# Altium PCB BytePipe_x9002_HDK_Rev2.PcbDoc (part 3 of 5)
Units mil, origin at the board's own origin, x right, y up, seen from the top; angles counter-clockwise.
Board outline 4250 x 4250 mil, 8 copper layers (Top Layer, L2-GND, L3-SIG, L4-GND, L5-PWR, L6-SIG, L7-GND, Bottom Layer), stack 63 mil thick; 296 components, 250 nets, 1198 pads, 2326 vias.
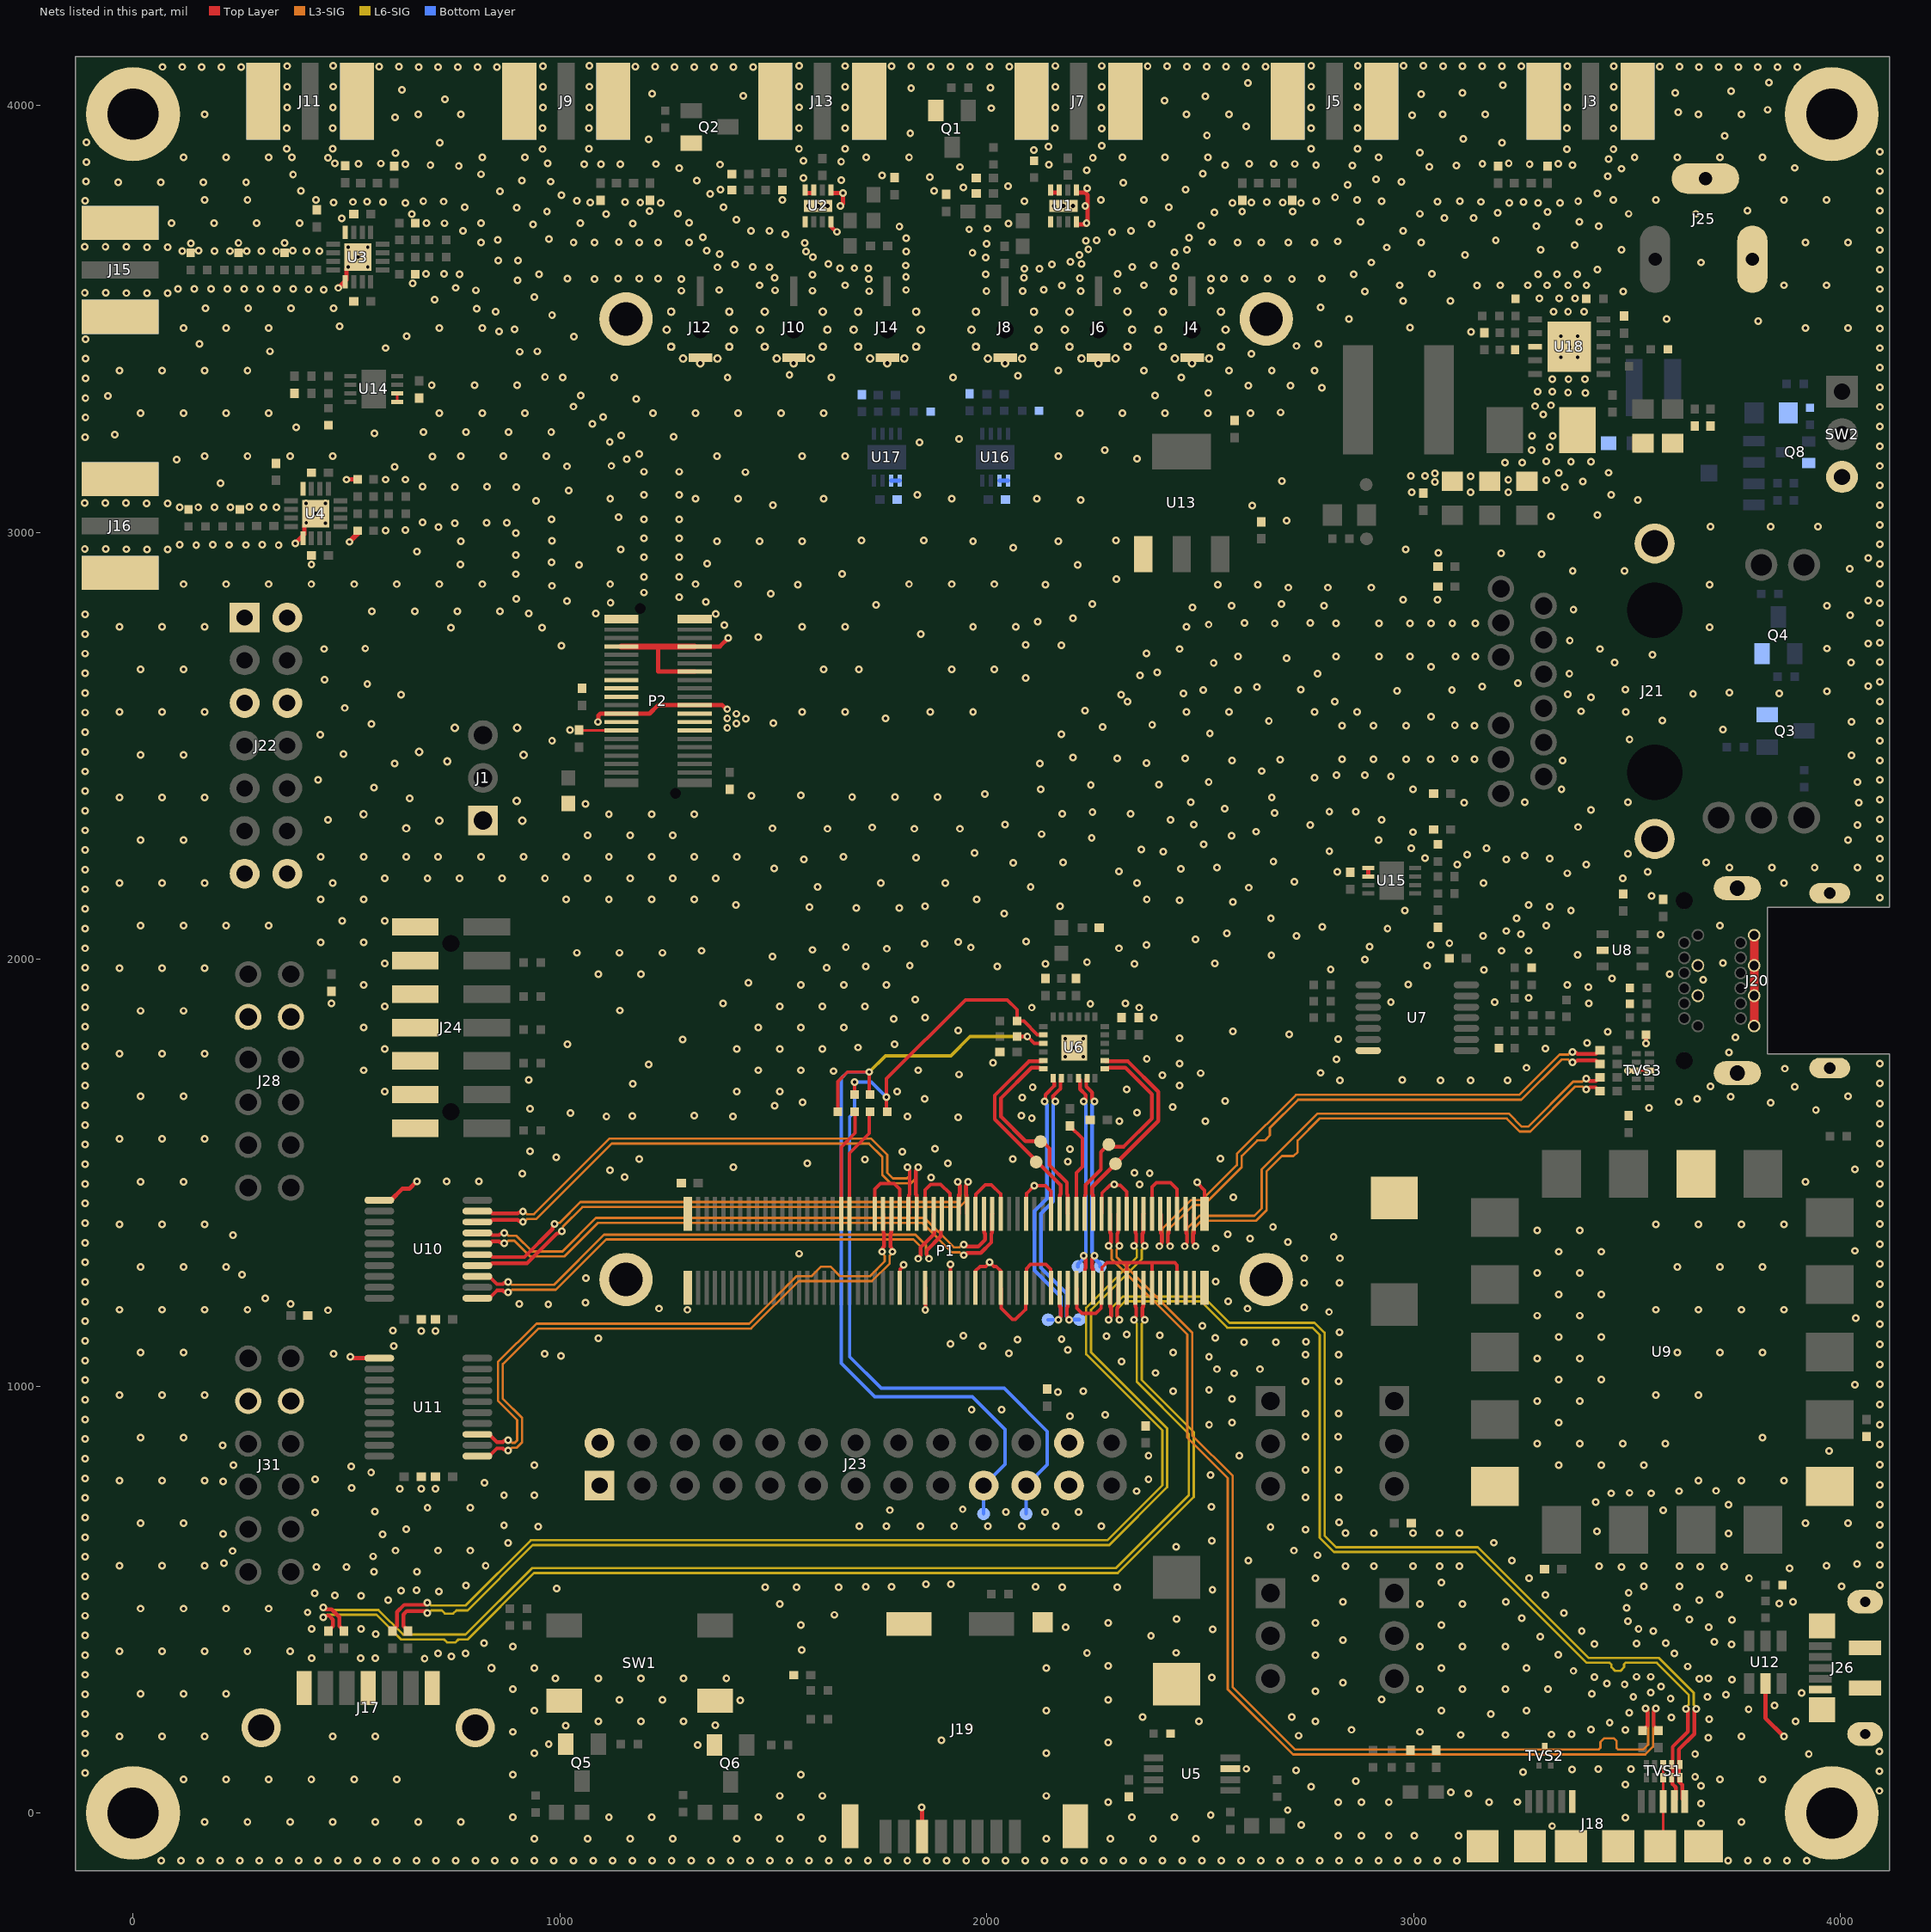
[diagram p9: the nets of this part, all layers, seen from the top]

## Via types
v1: diameter 18, hole 8, Top Layer to Bottom Layer, tented both sides, 2283 vias
v2: diameter 20, hole 10, Top Layer to Bottom Layer, tented both sides, 39 vias
v3: diameter 16, hole 8, Top Layer to Bottom Layer, tented both sides, 4 vias

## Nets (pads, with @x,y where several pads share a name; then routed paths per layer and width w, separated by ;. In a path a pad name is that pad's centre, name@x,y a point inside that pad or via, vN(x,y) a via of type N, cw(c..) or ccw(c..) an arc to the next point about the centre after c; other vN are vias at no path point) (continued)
GND: C1.2 C2.2 C3.2 C4.2 C5.2 C6.2 C7.2 C8.2 C9.2 C10.2 C11.2 C14.2 C15.2 C16.2 C17.2 C18.2 C19.2 C20.2 C23.2 C24.2 C26.2 C27.2 C28.2 C30.2 C33.2 C36.2 C37.2 C38.2 C39.2 C40.2 C43.2 C44.2 C45.2 C46.2 C47.2 C48.2 C49.2 C50.2 C51.2 C56.2 C57.2 C60.2 C61.1 C62.1 C63.1 C64.1 C65.2 C66.1 C67.2 C68.2 C69.1 C70.2 C71.2 C72.2 C73.1 C74.1 C75.2 C76.2 C77.2 C78.2 C79.2 C80.2 C82.2 C83.2 C85.2 C86.2 C88.2 C89.2 C91.2 C92.2 C93.2 C94.2 C95.2 C97.1 C98.2 C99.2 C100.2 C101.1 C102.1 C103.2 C104.2 D1.2 J1.1 J3.2 J4.2 J5.2 J6.2 J7.2 J8.2 J9.2 J10.2 J11.2 J12.2 J13.2 J14.2 J15.2 J16.2 J17.0 J17.1 J17.4 J17.7 J18.5 J18.8 J18.11 J18.12 J18.13 J18.14 J18.15 J18.16 J19.6 J19.M-1 J19.M-2 J19.M-3 J19.M-4 J20.0 J20.1 J20.7 J20.8 J20.13 J20.14 J20.19 J21.0 J22.1 J22.2 J22.5 J22.6 J22.13 J22.14 J23.1 J23.2 J23.23 J23.24 J24.1 J24.3 J24.5 J24.7 J24.9 J24.11 J24.13 J25.2 J25.3 J26.5 J26.SH J26.TH J28.5 J28.11 J31.5 J31.11 MH1.1 MH2.1 MH3.1 MH4.1 MH5.1 MH6.1 MH7.1 MH8.1 P1.05 P1.06 P1.11 P1.12 P1.17 P1.18 P1.23 P1.24 P1.29 P1.30 P1.35 P1.36 P1.41 P1.42 P1.47 P1.48 P1.53 P1.54 P1.59 P1.60 P1.65 P1.66 P1.71 P1.72 P1.77 P1.M1 P1.M2 P1.M3 P1.M4 P2.01 P2.02 P2.07 P2.08 P2.14 P2.15 P2.17 P2.19 P2.22 P2.23 P2.24 P2.25 P2.26 P2.27 P2.28 Q1.2 Q2.2 Q3.2 Q4.2 Q5.2 Q6.2 Q8.2 R2.1 R5.1 R13.2 R14.2 R15.2 R16.2 R17.2 R23.2 R24.2 R25.2 R26.2 R31.2 R38.1 R45.2 R46.2 R47.1 R50.1 R64.2 R67.1 R72.1 R74.1 R76.1 R80.1 R85.2 R86.2 R88.2 SW1.3 SW1.4 SW2.3 TVS1.3 TVS1.8 TVS2.3 TVS3.3 TVS3.8 U1.1 U1.3 U1.4 U1.5 U1.8 U1.9 U2.1 U2.3 U2.4 U2.5 U2.8 U2.9 U3.5 U3.16 U3.17 U4.5 U4.16 U4.17 U5.3 U6.25 U7.7 U8.2 U9.1 U9.7 U9.14 U10.11 U11.11 U12.5 U13.1 U14.5 U14.6 U15.5 U15.6 U16.5 U16.6 U17.5 U17.6 U18.8 U18.11 | length 4866.7
  Top Layer w6: R24.2@525.13,3123.91 R24.2@526.04,3124.81 ; U14.5@619,3306 U14.6@619,3326 ; C3.2@1045,2537 1045.9,2536.1 P2.27@1143.39,2536.1 ; C2.2@1393.39,2393.39 C2.2@1398,2398 ; TVS3.8@3524.5,1739 TVS3.3@3553.08,1739 TVS3.3@3555.5,1739 ; J18.15@3578,-78 3585,-71 TVS1.8@3585,82.5 TVS1.3@3585,113.5
  Top Layer w8: P1.77@1737.68,1403.61 1737.68,1461.68 1751,1475 1783.27,1475 1796.73,1461.54 P1.71@1796.73,1403.61 ; P1.72@1796.73,1230.39 1797.73,1231.39 1797.73,1274.03 1805,1281.29 v1(1805,1284) ; P1.65@1855.79,1403.61 1855.79,1459.79 1869,1473 1891.9,1473 1913.84,1451.06 1913.84,1404.61 P1.59@1914.84,1403.61 ; v1(1856.24,1178.31) 1857,1179.07 P1.66@1857,1231 ; P1.60@1914.84,1230.39 1915.42,1230.96 v1(1915.42,1285.42) ; P1.54@1973.9,1230.39 1973.9,1269.84 1984.44,1280.39 1997.39,1280.39 v1(2007,1290) 2016.61,1280.39 2022.41,1280.39 2032.95,1269.84 P1.48@2032.95,1230.39 2033.95,1229.39 2033.95,1182.94 2060.63,1156.26 2067.26,1156.26 2091.01,1180.01 2091.01,1229.39 P1.42@2092.01,1230.39 2093.01,1231.39 2093.01,1275.01 2102.93,1284.93 2120.93,1284.93 2138.93,1284.93 2150.06,1273.79 2150.06,1231.39 P1.36@2151.06,1230.39 ; P1.53@1973.9,1403.61 1974.9,1404.61 1974.9,1449.9 1997,1472 2011,1472 2033,1450 2033,1403.66 P1.47@2032.95,1403.61 ; P1.41@2092.01,1403.61 2093.01,1404.61 2093.01,1451 v1(2112.01,1470) 2138,1470 2151.06,1456.94 P1.35@2151.06,1403.61 ; C46.2@2195,1610 2195,1609 2224,1580 2224,1514 2210.12,1500.12 P1.29@2210.12,1403.61 ; P1.30@2210.12,1230.39 2211.12,1229.39 2211.12,1182.94 2223.67,1170.39 2255.56,1170.39 2268.17,1183 2268.17,1229.39 P1.24@2269.17,1230.39 2270.17,1231.39 2270.17,1277.77 2281.4,1289 2332,1289 ; P1.23@2269.17,1403.61 2270.17,1404.61 2270.17,1452.17 2289,1471 2312.84,1471 2328.23,1455.61 P1.17@2328.23,1403.61 ; P1.18@2328.23,1230.39 2328.23,1285.23 2332,1289 ; P1.12@2387.28,1230.39 2387.28,1289 ; P1.11@2387.28,1403.61 2387.28,1466.28 2398,1477 2431,1477 2446.34,1461.66 P1.05@2446.34,1403.61 ; P1.06@2446.34,1230.39 2446.34,1283.66 2441,1289 2387.28,1289 ; v1(2493,1478) 2493,1476.24 2510.31,1458.92 P1.M1@2510.31,1403.61 ; 2332,1289 2387.28,1289
  Top Layer w10: v1(380.14,2974.49) 401,2995.35 401,3017 U4.17@428,3044 ; v1(481,3572.96) 500,3591.96 500,3618 v1(504,3622) v1(527,3645) ; v1(500.04,3123.81) 500.13,3123.91 525.13,3123.91 525.91,3123.91 R24.2@526,3124 ; v1(509,1069) 511.16,1069 514.66,1065.5 U11.11@577,1065.5 ; U10.11@577,1435.5 604,1435.5 630.82,1462.32 647.32,1462.32 v1(665,1480) ; v1(1089.02,2555.86) 1090.55,2557.39 1090.55,2571.15 1094.87,2575.47 P2.23@1144,2575.47 1210.31,2575.47 1230,2595.16 P2.22@1316,2595.16 1380.68,2595.16 1389.84,2586 v1(1392,2586) ; P2.07@1143.39,2732.95 P2.07@1144,2732.95 ; 1230,2732.95 1230,2673.9 P2.14@1316,2673.9 P2.14@1316.61,2673.9 ; P2.08@1316,2732.95 1374.98,2732.95 v1(1394.79,2752.76) ; P2.02@1316,2797 P2.02@1317.35,2798.35 ; U2.4@1575,3795 U2.3@1595,3795 ; U2.8@1635,3721 1635,3717 1648.02,3703.98 v1(1648.88,3703.98) ; U2.1@1635,3795 v1(1663,3795) v1@1663,3770 ; v1(1848,13) 1848.5,12.5 1848.5,-60.5 J19.6@1849,-61 ; U1.4@2150,3796 U1.3@2170,3796 ; U1.8@2210,3722 2231,3722 v1(2233.93,3724.93) 2236.86,3727.86 2236.86,3790.14 2231,3796 U1.1@2210,3796 ; U15.6@2894,2194 U15.5@2894,2214 ; v1(3502,1739) TVS3.8@3522.08,1739 TVS3.8@3524.5,1739 ; v1(3545,1803) R50.1@3545,1823 ; U12.5@3824.5,303 3824.5,222.56 v1(3868.03,179.03)
  Top Layer w12: v1(507.04,2977.81) 526,2996.77 R23.2@526,3004
  Top Layer w14: P2.07@1144,2732.95 1230,2732.95 P2.08@1316,2732.95
  Top Layer w20: J20.1@3798.11,1843.7 J20.7@3798.11,1914.57 J20.13@3798.11,1985.43 J20.19@3798.11,2056.3
  Bottom Layer w10: U17.6@1776,3121 U17.5@1796,3121 ; U16.6@2030,3121 U16.5@2050,3121
  other v1: 66,-112 112,-112 158,-112 204,-112 250,-112 296,-112 342,-112 388,-112 434,-112 480,-112 526,-112 572,-112 618,-112 664,-112 710,-112 756,-112 802,-112 848,-112 894,-112 940,-112 986,-112 1032,-112 1078,-112 1124,-112 1170,-112 1216,-112 1262,-112 1308,-112 1354,-112 1400,-112 1446,-112 1492,-112 1538,-112 1584,-112 1630,-112 1676,-112 1722,-112 1768,-112 1814,-112 1860,-112 1906,-112 1952,-112 1998,-112 2044,-112 2090,-112 2136,-112 2182,-112 2228,-112 2274,-112 2320,-112 2366,-112 2412,-112 2458,-112 2504,-112 2550,-112 2596,-112 2642,-112 2688,-112 2734,-112 2780,-112 2826,-112 2872,-112 2918,-112 2964,-112 3010,-112 3056,-112 3102,-112 3737,-112 3783,-112 3829,-112 3875,-112 3921,-112 940,-60 1065,-60 1165,-60 1265,-60 1415,-60 1515,-60 1615,-60 2140,-60 2290,-60 2390,-60 2490,-60 3105.37,-53.63 2823.19,-53.06 2878,-53 2942,-53 3001.77,-53.06 3324.72,-30.53 2736.76,-28.45 3674,-24 168.03,-20.97 268.03,-20.97 368.03,-20.97 468.03,-20.97 568.03,-20.97 668.03,-20.97 768.03,-20.97 3768.03,-20.97 3496,-11 890,-10 1115,-10 1215,-10 1465,-10 1565,-10 2340,-10 2440,-10 2525,-5 2705.27,6.7 3674,22 2285,25 2823.19,24.94 2878,25 2942,25 3177.54,25.7 3243.82,25.86 1515,40 1615,40 2140,40 3128.44,45.4 3087.1,48.63 4092,52 2760.42,61.85 3674,64 3496,67 2865,75 118.03,79.03 218.03,79.03 318.03,79.03 418.03,79.03 518.03,79.03 618.03,79.03 3718.03,79.03 3818.03,79.03 3660,85 890,90 1565,90 -112,94 3257.13,95.55 4092,98 2725,100 3371.23,102.09 2608.57,103.4 3433.16,102.78 3509.17,103.01 3660,138 3926,138 -112,140 940,140 2140,140 4092,144 1323,159 974,161 2285,165 1894,170 3691.15,176.15 -31.97,179.03 68.03,179.03 168.03,179.03 468.03,179.03 568.03,179.03 3768.03,179.03 2731,181 3111,183 3215,183 3323,184 3370.84,184.51 -112,186 890,190 3015,190 3496.81,194.37 2855,195 3415.4,195.65 1960,202 1014,205 1364,206 3459.61,211.31 2497.67,214.29 1090,215 1190,215 1290,215 2770,215 3895,215 3693,220 3604,224 2365,225 2715,225 -112,232 3181,232 3505.85,234.85 940,240 2140,240 3065,240 3265,240 3785,243 3846,252 1423,264 1140,265 1240,265 2285,265 2925,266 3602.59,268.26 3515,272 3689.15,271.85 3732,277 -112,278 18.03,279.03 118.03,279.03 218.03,279.03 3418.03,279.03 3909,281 3556,282 2770,285 890,290 3015,290 3115,290 3215,290 3315,290 3580,296 3494.85,301.15 3453,303 2835,305 3746,312 3670,314 990,315 1090,315 1190,315 1290,315 1390,315 3691,315 2527.32,317.03 3424,318 3523,319 3556,319 -112,324 3375,333 940,340 2140,340 3065,340 3265,340 3642.15,343.15 2285,345 683,362 419,363 533,363 568,363 746,367 -112,370 2770,370 3339,371 715,374 779,374 3611.15,374.15 2235,375 2443.55,375.31 -31.97,379.03 68.03,379.03 168.03,379.03 268.03,379.03 368.03,379.03 1567,382 890,390 3015,390 3115,390 3215,390 3745,395 3424,396 3523,397 822,398 3591,398 3704.85,401.15 2835,405 3297,413 2385,415 -112,416 569,419 3394.15,426.15 3562,426 2529.31,430.41 419,431 534,431 3527.15,430.85 2185,435 3692,435 1565,440 3065,440 2285,445 2770,445 3502,449 3746,452 3646.15,453.15 2444.88,454.27 3254,456 -112,462 1643,464 3352.15,468.15 409,470 18.03,479.03 118.03,479.03 218.03,479.03 318.03,479.03 3499,481 3617.15,481.15 1515,490 3015,490 3115,490 3857,491 2835,495 3216,495 3889,495 598,499 3670,499 -112,508 534,509 473,510 3309.15,511.15 3717,512 426,515 3504,516 717,519 628,521 664,522 2529.02,522.99 993,526 1481,529 1555,529 1653,529 2177,529 2306,529 1717,530 1777,530 2115,530 3540,531 3623,531 4003,531 780,533 4093,534 1858,536 1916,536 3065,540 2770,550 3271.15,550.15 3786,550 -112,554 565,565 665,565 3881,573 430,576 500,576 3487.77,576.23 3672,577 3728,577 2841,578 2907,578 2999,578 3061,578 3108,578 3435,578 3540,578 3623,578 -31.97,579.03 68.03,579.03 168.03,579.03 826,579 3968.03,579.03 4093,581 4039,583 213,585 2613.39,591.09 3230.15,591.15 -112,600 563,601 2775,604 233,614 615,615 715,615 790,615 2720,615 2444.31,623.39 4093,628 879,633 3188.15,633.15 2527.14,637.67 -112,646 585,653 211,654 3738,655 2841,656 2907,656 2999,656 3061,656 3108,656 3430,660 2747,664 640,665 2665,670 949,671 1702,672 1765,672 1844.4,672 1923.8,672 2003.2,672 2082.6,672 2162,672 2269,672 869.29,673.58 4093,675 18.03,679.03 118.03,679.03 3918.03,679.03 4018.03,679.03 2826,681 -112,692 427,704 2045,705 2137.14,705 2215,705 567,706 3585,709 1773.28,709.65 1943.91,711.69 690,715 790,715 2526.21,717.08 3738,722 4093,722 3427,728 -112,738 2747,739 2825,739 869.29,744.29 940,744.29 3463,749 3557,749 3506,750 2351,754 3622,754 3709,755 625,760 675,760 709,760 511.85,761.15 4093,769 823.58,773.58 211,777 -31.97,779.03 68.03,779.03 168.03,779.03 3668.03,779.03 3768.03,779.03 3868.03,779.03 427,782 2379,782 -112,784 2524.66,791.84 558,798 2747,804 2825,804 511,812 235,815 940,815 3340,815 3440,815 3540,815 4093,816 -112,830 2379,837 2591.94,836.89 3974,848 210,861 4093,863 3290,865 3390,865 3490,865 3590,865 -112,876 18.03,879.03 118.03,879.03 3818.03,879.03 2747,881 2824,881 2521.01,909.48 4093,910 2575,915 3340,915 -112,922 2195,930 2277.81,932.79 2747,936 2825,936 1965,945 2035,945 4093,957 3290,965 3390,965 -112,968 2575,970 -31.97,979.03 68.03,979.03 168.03,979.03 3568.03,979.03 3668.03,979.03 2167,986 2226.25,988.46 2437,988 2521,991 4034,1003 4093,1004 2747,1011 2825,1011 -112,1014 3340,1015 3440,1015 2580,1030 2396,1031 2540,1040 2640,1040 4093,1051 2316,1058 -112,1060 3290,1065 3390,1065 2521,1069 1003,1071 2747,1074 2825,1074 470,1076 964,1076 2052,1077 18.03,1079.03 118.03,1079.03 2437,1079 3618.03,1079.03 3718.03,1079.03 3818.03,1079.03 2189.81,1084.9 611,1094 1991,1094 4093,1098 1915,1099 2603,1103 2678,1103 2748,1104 -112,1106 2072,1109 2175.54,1110.43 1090,1112 2536,1113 3340,1115 3440,1115 2281,1117 1945,1118 2405.95,1119.39 2328,1121 2827,1126 675,1129 709,1129 609,1130 2505,1141 4093,1145 -112,1152 4036,1159 3290,1165 3390,1165 2802,1173.95 457,1178 -31.97,1179.03 68.03,1179.03 168.03,1179.03 268.03,1179.03 1299,1179 3568.03,1179.03 3668.03,1179.03 3768.03,1179.03 3868.03,1179.03 1232,1182 2611,1182 2744,1184.62 973,1192 4093,1192 369,1193 905,1193 1060,1196 -112,1198 2566,1199 310.15,1205.85 3340,1215 3440,1215 4093,1239 2744,1242.23 2827,1241.9 -112,1244 2537,1245 1061.15,1253.15 255,1261 3290,1265 3390,1265 18.03,1279.03 118.03,1279.03 218.03,1279.03 3618.03,1279.03 3718.03,1279.03 3818.03,1279.03 4093,1286 -112,1290 2744,1299.85 2828,1299.85 1561,1310 3340,1315 3440,1315 4034,1317 2537,1323 4093,1333 -112,1336 2706,1338 2616.85,1345.85 2813,1350 233.85,1353.85 2565.15,1356.15 3290,1365 3390,1365 2671,1373 -31.97,1379.03 68.03,1379.03 168.03,1379.03 3568.03,1379.03 3668.03,1379.03 3768.03,1379.03 3868.03,1379.03 4093,1380 -112,1382 4093,1427 -112,1428 2578.29,1442.07 2299,1473 2358,1473 -112,1474 4093,1474 18.03,1479.03 118.03,1479.03 3918.03,1479.03 735,1480 810,1480 1870,1489 1151.85,1490.15 912,1498 2382,1499 2346.33,1500 1117.49,1505.88 4034,1508 1407,1513 -112,1520 4093,1521 1580,1522 1909,1522 2190,1526 1714.69,1530.63 1186,1532 2061,1532 2548,1533 992,1536 1802,1549 930,1550 2195,1555 1879,1556 -112,1566 4093,1568 -31.97,1579.03 68.03,1579.03 168.03,1579.03 -112,1612 4093,1615 2311,1621 2512,1621 2106,1627.78 1933,1630 1109,1632 1406,1632 1814.86,1632 1170,1633 1315,1634 2081,1634 1025,1640 2352,1641 3943,1647 930,1650 3552,1652 2436,1654 1503.29,1657.05 -112,1658 4093,1662 3837,1664 1569,1665 3621,1666 2559,1668 1855,1673 3665,1673 2083,1676 3743,1678 18.03,1679.03 118.03,1679.03 4018.03,1679.03 590,1690 1415,1690 1515,1690 1790,1690 2328,1695 2108,1700 3893,1701 3696,1702 -112,1704 2452,1704 1171,1708 4093,1709 2828,1716 3063,1716 3134,1716 3220,1716 927,1717 2974,1717 2412,1728 1935,1730 2501,1733 2782,1734 1641,1738 540,1740 1465,1740 1565,1740 1840,1740 3870,1744 3265,1746 -112,1750 1208,1754 2452,1756 4093,1756 2014.54,1757.29 2820,1766 2375,1767 2184,1772 2226,1772 -31.97,1779.03 68.03,1779.03 168.03,1779.03 3739,1782 590,1790 1415,1790 1515,1790 1615,1790 3309,1791 1698.58,1793.42 2205,1793 -112,1796 1018,1801 1784,1801 3407,1804 1288,1812 2824,1812.67 2184,1814 2226,1814 2452,1815 3754,1817 2709,1824 3455,1830 2577,1831 1933,1833 540,1840 1465,1840 1565,1840 1665,1840 -112,1842 1782.58,1860.42 1856,1863 2391.25,1863 18.03,1879.03 118.03,1879.03 1141,1880 2106,1887 2357,1887 -112,1888 590,1890 1515,1890 1615,1890 1715,1890 2243,1896 465,1897 1382,1897 2325,1897 3411,1897 2947,1900 3190,1900 1832.58,1905.42 3270,1910 -112,1934 3410,1935 540,1940 1565,1940 1665,1940 1765,1940 3360,1940 2988,1941 1442,1945 3679,1952 3465,1955 1090,1965 1190,1965 3600,1965 3165,1975 2806,1976 -31.97,1979.03 68.03,1979.03 168.03,1979.03 -112,1980 1625,1980 1717,1983 2025,1983 1820,1985 3032,1985 2138,1989 2346.33,1989 590,1990 2535,1990 3725,1991 2235,1993 2886,1999 1498,2006 2667,2009 3385,2010 1040,2015 1140,2015 1240,2015 1332,2020 3206,2020 3270,2020 1592,2022 1766,2025 -112,2026 2310,2026 1963,2028 1670,2029 2897,2030 3040,2033.47 2374,2034 1855,2037 3084,2038 440,2040 540,2040 1933,2041 2092,2042 2489,2047 2726,2055 3163,2055 3579,2058 3252,2059 2563,2061 3217,2066.33 -112,2072 2939,2072 2786,2076 18.03,2079.03 118.03,2079.03 218.03,2079.03 318.03,2079.03 3311.37,2079 3718.03,2079.03 490,2090 590,2090 2666,2096 3241.37,2096 2041,2107 2980,2114 3368.99,2114 -112,2118 1695,2120 1795,2120 1585,2122 3319,2122.89 1856,2124 2172,2124 1413,2127 3270,2127.07 2577,2134 2452,2138 440,2140 540,2140 1015,2140 1115,2140 1215,2140 1315,2140 1977,2140 2375,2140 4093,2144 3558,2148 -112,2164 2614,2168 1604,2170 2103,2170 -31.97,2179.03 68.03,2179.03 168.03,2179.03 468.03,2179.03 1752,2179 1903,2179 2352,2179 3164,2179 3868.03,2179.03 2721,2182 590,2190 690,2190 765,2190 865,2190 965,2190 1065,2190 1165,2190 1265,2190 1365,2190 3490,2190 4093,2190 3360,2201.33 2822,2205 3548.61,2205.07 2310,2206 -112,2210 2455,2212 1502,2213 2540,2215 3740,2215 3840,2215 3940,2215 4040,2215 3103,2222 3405,2222 2062,2226 2179,2227 3686,2227 2672,2229 1572,2234 3217,2234 3319,2236 4093,2236 3027,2237 1835,2238 440,2240 540,2240 640,2240 715,2240 815,2240 915,2240 1015,2240 1115,2240 1215,2240 1315,2240 1415,2240 1664,2240 3261,2242.77 3126,2245 3502,2247.32 1972,2249 2414,2252 2803,2253 -112,2256 2362,2257 2995,2260 3171,2260 2508,2269 18.03,2279.03 118.03,2279.03 2918.03,2279.03 4018.03,2279.03 4093,2282 2246,2284 2574,2289 1065,2290 1165,2290 1265,2290 2129,2293 2999,2298 2631,2299 -112,2302 1627,2306 1831,2306 1937,2306 1498,2307 1732,2309 3386,2310 2758,2315 4040,2315 2043,2316 2485,2316 457,2327 2431,2327 2924.98,2327 4093,2328 1115,2340 1215,2340 1315,2340 2177,2341 2337,2341 2675,2343 2248,2345 2803,2346.23 2864.98,2346.23 -112,2348 3416,2350 2558,2353 1060,2364 3119,2367 4043,2367 2478,2368 3261,2368.33 3502,2368.33 4093,2374 648,2377 -31.97,2379.03 68.03,2379.03 168.03,2379.03 2668.03,2379.03 1685,2380 1785,2380 1885,2380 1449,2383 1565,2384 1996,2387 -112,2394 2127,2398 2999,2398 3346.82,2398 565,2402 2244,2408 2404,2409 2520,2415 4040,2415 434,2420 4093,2420 2768,2425 2947,2428 2820,2431.63 2886,2431.63 -112,2440 2644,2441 613,2459 2125,2459 2374,2460 2575.01,2466 3349.55,2466 4093,2466 2687.28,2468 2833,2469 2906,2469 2983,2469 3040,2469 3143,2469 3097,2470 2306,2471 2465,2471 2202,2473 4026,2478 18.03,2479.03 118.03,2479.03 493,2481 -112,2486 982,2512 4093,2512 3506,2515 439,2526 2175,2527 2523,2529 -112,2532 1023.98,2537.08 3725,2538 1392,2542 2272,2544 2833,2547 2906,2547 2983,2547 3143,2547 3097,2548 2388,2549 559,2551 1414,2552 1500,2553 4026,2556 2661,2558 4093,2558 3583,2559 1436,2563 1392,2564 1762.73,2564 3041,2568 1414,2575 -112,2578 -31.97,2579.03 68.03,2579.03 168.03,2579.03 1568.03,2579.03 1668.03,2579.03 1868.03,2579.03 1968.03,2579.03 2468.03,2579.03 2568.03,2579.03 2768.03,2579.03 2868.03,2579.03 3497.23,2579.03 3393,2581 2230.15,2582.15 496,2589 2330,2604 2815.74,2604 4093,2604 3416,2613.72 628,2620 2315,2620 3361,2621 3655,2622 2461,2623 3857,2623 -112,2624 3740,2625 3969,2628 2962,2629 2507,2631 2589,2631 3090,2631 2736,2632 3496,2632 2633,2638 3161,2639 4065,2640 549,2645 3245,2647 4093,2650 449,2655 2091,2659 2359,2665 2775.37,2669 3365,2669 -112,2670 2400,2672 18.03,2679.03 118.03,2679.03 1618.03,2679.03 1701,2679 1918.03,2679.03 2018.03,2679.03 3041,2685 2532,2694 3471,2695 4025,2695 4093,2696 2703,2705 2589,2709 2819,2709 2919,2709 2992,2709 3099,2709 3145,2709 3560,2713 -112,2716 2374.33,2716.67 448,2727 2452.25,2727 3437,2727 544,2728 3969,2728 1003.53,2734.59 2175,2736 2091,2737 4065,2740 4093,2742 3366,2747 1465,2755 -112,2762 1846,2762 745,2777 958.32,2777.09 3694,2778 -31.97,2779.03 68.03,2779.03 168.03,2779.03 1568.03,2779.03 1668.03,2779.03 1968.03,2779.03 2068.03,2779.03 2468.03,2779.03 1385.66,2782.5 2520,2784.37 2675.03,2787 2819,2787 2919,2787 2992,2787 3041,2787 3091,2787 3145,2787 2604.12,2788 2758,2788.02 4093,2788 2119.85,2791.15 2202,2799.26 4023,2806 -112,2808 1365,2809 926.85,2809.86 1084.16,2809.86 560,2815 660,2815 760,2815 860,2815 3375,2819 2482.63,2824.37 2573.55,2828 2789.99,2828 3969,2828 1741,2830 2247.63,2832.41 2691.04,2832.41 4093,2834 1119,2835 1342,2837 1016.98,2839.03 4065,2840 2975.66,2842 3056,2842 897.62,2844.3 1280,2848 1494,2856 1197,2859 2707,2871 2799.37,2871 2901.08,2871 981.55,2875.02 1558,2878 2138,2878 2541.63,2878 2634.99,2878 3694,2878 118.03,2879.03 218.03,2879.03 318.03,2879.03 418.03,2879.03 518.03,2879.03 618.03,2879.03 718.03,2879.03 818.03,2879.03 1118.03,2879.03 1318.03,2879.03 1418.03,2879.03 1818.03,2879.03 1918.03,2879.03 2018.03,2879.03 4093,2880 2304.32,2890.72 1197,2896 1280,2896 897.19,2902.27 1661,2903 3373,2910 3494,2910 4022,2915 1045,2924 2212.9,2924 418.04,2924.81 767,2925 4093,2926 1345,2927 980.25,2930.39 4065,2940 1197,2942 1280,2942 897.19,2947.26 3300,2949 3205,2951 3058,2952 665,2955 32.76,2960.23 81.27,2960.23 1143,2960 2982.02,2960.37 -112.76,2960.86 -64.25,2960.86 -15.74,2960.67 2062,2964.26 148.14,2970.47 341.48,2970.47 109.47,2970.97 186.81,2970.97 225.47,2970.72 264.14,2970.72 302.81,2970.97 4093,2972 768.03,2979.03 1368.03,2979.03 1468.03,2979.03 1568.03,2979.03 1968.03,2979.03 2168.03,2979.03 981.98,2980.57 1707,2981 1853,2981 2303.37,2981 1197,2986 1280,2986 896.84,2998.86 592.04,3004.81 638.04,3005.81 716.04,3012.81 3696.23,3013.23 3836.38,3013.23 3947.45,3013.23 4093,3018 451.04,3021.81 754,3022 875.44,3022.2 406,3023 828.7,3022.55 678.04,3023.81 2703,3027.58 980.94,3030.62 1197,3031 1280,3031 1138,3036 3321.96,3037.62 3430.73,3041 428.04,3044.81 109.19,3058.95 153.14,3059.23 190.9,3058.66 228.37,3059.23 272.89,3059.51 305.78,3059.3 336.36,3059.01 2621.79,3062.5 1499,3064 4093,3064 32.25,3068.16 80.76,3068.16 405.04,3067.81 451.04,3067.81 -113.28,3068.78 -64.77,3068.78 -16.26,3068.59 944.23,3074.1 2220.12,3075.65 3525.77,3075.84 1118.03,3079.03 1318.03,3079.03 1418.03,3079.03 1618.03,3079.03 1918.03,3079.03 2118.03,3079.03 1197,3088 1280,3088 1838,3088 3463,3088 2996,3094 3134,3094 3222,3094 1021,3098 754,3106 898.29,3106.33 3354,3106 678.04,3106.81 829.39,3107.02 4093,3110 205,3115 3050,3118 3397,3119 2692.07,3120.12 3311,3122 3222,3123 592.04,3123.81 638.04,3123.81 3134,3131 2994,3132 3027,3132 3050,3138 3340,3139 3457.07,3139.96 1435,3141 1197,3142 1280,3142 612.61,3153.87 1017,3155 1121,3156 4093,3156 3214,3164 3255,3164 3369,3166 3416,3166 3311,3167 102,3171 1157,3172 2352,3172.6 702,3178 168.03,3179.03 268.03,3179.03 368.03,3179.03 468.03,3179.03 768.03,3179.03 868.03,3179.03 968.03,3179.03 1368.03,3179.03 1568.03,3179.03 1668.03,3179.03 2168.03,3179.03 1186,3184 2276.37,3193 3277,3193 3319,3200 4093,3202 1843,3211 1117,3212 1935,3219 -112,3223 1267,3224 3278,3226 3326,3226 1144,3227 -43,3229 566,3232 680,3235 780,3235 880,3235 980,3235 382,3246 4093,3248 1076,3254 -111.63,3269 1101,3270 3304,3276 18.03,3279.03 118.03,3279.03 218.03,3279.03 318.03,3279.03 718.03,3279.03 818.03,3279.03 918.03,3279.03 1218.03,3279.03 1318.03,3279.03 1418.03,3279.03 1518.03,3279.03 1618.03,3279.03 2218.03,3279.03 2318.03,3279.03 2418.03,3279.03 2518.03,3279.03 2618.03,3279.03 2689,3281 4093,3294 1032,3295 3285,3296 3322,3298 1179,3313 -111.63,3315 -59,3320 1049,3321 2395,3321 2519,3327 3403,3327 3362,3328 3291,3330 3325,3330 2785.42,3338.74 4093,3340 2613,3344 2712,3344 700,3345 800,3345 900,3345 3325,3359 3363,3359 3402,3359 -111.44,3361 1007,3363 1128,3363 1393,3363 1636,3363 1921,3363 2456,3363 965,3364 2073,3367 1538,3369 -31.97,3379.03 68.03,3379.03 168.03,3379.03 268.03,3379.03 2168.03,3379.03 2368.03,3379.03 2568.03,3379.03 2668.03,3379.03 2768.03,3379.03 4093,3386 -111,3407 3345,3410 3385,3410 2620,3418 906,3423 321,3424 947,3424 592,3432 4093,3432 3365,3435 2726,3437 156,3442 2777,3442 -111,3453 1033,3459 641,3460 3345,3460 3385,3460 3135,3470 858,3471 894,3476 4093,3478 118.03,3479.03 218.03,3479.03 318.03,3479.03 718.03,3479.03 818.03,3479.03 3918.03,3479.03 4018.03,3479.03 2992,3480 484,3483 3808,3495 2848.42,3500 3592.74,3500 982,3509 850,3517 3327.96,3517 3361.98,3517 3399.63,3517 805,3524 4093,3524 170,3525 270,3525 370,3525 470,3525 2782,3527 2975.99,3542.62 3086.74,3542.62 707,3545 3294.96,3548.5 3341.37,3548.5 3378.33,3548.5 940,3551 32.77,3560.45 81.28,3560.45 -112.76,3561.08 -64.25,3561.08 -15.74,3560.89 1725,3565 1999.34,3565.46 2084.74,3565.29 2437.66,3564.86 2886.38,3564.56 3491.65,3564.56 1285,3566 1592,3566 2220.12,3565.72 2306.36,3565.92 2525.01,3566.41 803,3567 1504,3567 1373,3568 1811,3568 446.83,3568.91 2133.81,3568.69 144.01,3570.42 337.35,3570.42 375.67,3570.19 411.4,3569.9 4093,3570 105.35,3570.92 182.68,3570.92 221.35,3570.67 260.02,3570.67 298.69,3570.92 756,3573 2175.64,3578.39 3148.74,3578.39 1468.03,3579.03 1668.03,3579.03 2368.03,3579.03 2968.03,3579.03 3203.65,3579.03 3267.98,3579.03 3313.02,3579.03 3362,3579.03 3405.26,3579.03 3868.03,3579.03 3968.03,3579.03 654.87,3583.31 901,3591 1723.91,3593.39 1081.35,3593.96 1136.42,3594.49 1186.16,3594.44 1284.96,3594.07 2658.59,3594.47 2715.3,3594.02 2785.42,3594.47 1017.81,3595.02 1230.22,3594.81 2217.96,3595.3 2525.41,3594.83 2555.87,3594.91 2604.1,3594.91 2436.97,3596.09 1502.83,3596.66 2087,3597 1810.93,3598.33 1591.56,3603.49 1997.98,3604.3 765,3605 951.09,3604.55 2307.09,3605.43 2859.55,3604.74 3042.98,3605.43 3292.02,3604.74 3335.96,3604.74 3383.33,3604.74 686.88,3606 728.62,3605.8 3430.73,3616 4093,3616 2088,3618 2124,3618 1656.63,3618.84 1690.07,3619.35 1723.21,3619.16 1369.38,3621.32 1490.85,3621.35 550,3622 1451.91,3621.67 2340.81,3621.56 2442.89,3623.94 1810.59,3625.39 2391.23,3625.73 1410.37,3628.17 2153,3628 1629.07,3628.8 2222,3629 2901.53,3632.43 3674,3632.43 2196,3634 856,3637 902.38,3637.38 1998,3644 1592.67,3645.3 2217,3650 3121.02,3650 1374.03,3651.85 1967,3655 2439.56,3656.33 1577,3658 1811.09,3657.86 115.1,3659.52 190.96,3659.28 226.87,3659.17 266.27,3658.89 300.54,3658.89 335.54,3659.25 406.15,3659.25 436.44,3659.5 153.77,3660.03 374.1,3660 1344.33,3660.47 2469.24,3662.35 3297.9,3662 3487.01,3662 4093,3662 2238,3663 32.6,3668.39 81.11,3668.39 504,3668 550,3668 2937.7,3667.7 -112.93,3669.02 -64.42,3669.02 -15.91,3668.82 3377.26,3673.5 2000,3676 135.13,3677.11 246.91,3678.2 354.9,3677.93 1574.14,3678.04 815,3679 1032.39,3678.93 1081.35,3679.33 1186.16,3679.44 1230.22,3679.33 1302.52,3678.96 2587.58,3679.32 2642.96,3678.87 2706.84,3679.46 2768,3678.95 3018.03,3679.03 3918.03,3679.03 4018.03,3679.03 1138.17,3679.88 2528.63,3679.76 2822.88,3681.76 2232,3683 2257.61,3684.06 3192.74,3684.06 855,3685 974.9,3686.97 1811.09,3689.76 2473.98,3690.06 1335.39,3691.68 1528.83,3698.53 2293.52,3703.24 773.4,3706.09 1448.05,3706.08 1491.14,3706.38 2975.66,3706.11 2338.51,3706.73 4093,3708 1959,3710 2002,3712 1795.79,3716.21 3287.74,3717.38 3434.35,3717.38 2502.5,3718.57 937.51,3721.95 2386.35,3722.88 687.29,3724.32 730.04,3724.12 815.44,3724.25 1171,3724 2051,3724 90,3725 190,3725 290,3725 390,3725 1048,3725 1302.48,3725.41 2875.82,3727.3 3389.01,3727.3 1413.39,3732.3 489,3736 3072.01,3737 3141.02,3737 653,3745.81 1108.42,3745.56 3015.41,3746.3 3504.01,3746.3 3661.5,3746.3 1277,3747 3197.16,3748.53 2533.44,3749.86 3314.17,3750.77 970,3752 2598.52,3751.75 2716.52,3751.75 1209.92,3752.57 3782.55,3754 4093,3754 898.92,3760.55 776.83,3762.18 1383.56,3761.83 2426.41,3762.08 2230.91,3764.49 1657,3765 637.97,3772.35 1236.24,3771.9 2575.86,3772.12 2736.5,3771.77 3224.41,3772.2 3291.67,3772.12 3343.64,3771.75 469.64,3772.69 1071.05,3772.98 1188.52,3773.13 2620.02,3772.81 2693.39,3772.81 515.03,3774.38 585.48,3773.7 1152.73,3773.55 2656.88,3773.86 3158.31,3774.44 3257.45,3773.54 548.9,3774.72 727.38,3775.39 3056.49,3774.88 679.97,3775.73 2088,3776 2772.31,3776.29 2925.34,3776.25 3108.74,3776.22 3386.07,3776.22 -112,3777 1039.71,3776.9 168.03,3779.03 268.03,3779.03 428.66,3778.78 1521,3779 2268.03,3779.03 2368.03,3779.03 2868.03,3779.03 3468.03,3779.03 3568.03,3779.03 3868.03,3779.03 3968.03,3779.03 2816.12,3784.98 1004.15,3790.46 1352.52,3792.87 3430.73,3794.08 393.44,3800.12 859.52,3799.55 1877,3800 4093,3800 1376,3803 2466.47,3803.01 2235.02,3806.12 1945,3808 2050,3811 2846.03,3814.19 2320,3819 -35,3820 65,3820 165,3820 265,3820 2972.01,3821.21 -110,3822 978.83,3821.8 911,3824 1321.18,3824.51 1659.61,3825.44 2912,3827 1570.58,3830.27 1867,3832 3455.29,3834.27 1755,3836 374.81,3838.39 815.29,3838.94 2506.54,3840.03 4093,3846 2234.81,3848.56 3487,3852 1279.89,3853.14 3893,3854 1937,3856 3037.46,3856.5 763.47,3858.42 697.01,3860.24 2558.36,3860.5 2856.51,3859.77 3100.64,3859.92 3372.91,3860.39 2145.8,3861.52 2771.74,3860.94 1375,3862 638.13,3862.82 1057.49,3862.78 1096.66,3862.78 1141.57,3862.78 1225.04,3863.09 2721.67,3863.11 3161.54,3863.33 3272.27,3862.61 3339.68,3863.38 528.14,3863.86 580.64,3864.12 2615.41,3863.55 2672.89,3863.55 473.2,3864.77 971.6,3864.89 3223,3865 -109.56,3868 1658.9,3868.79 1571.12,3870.58 3457.07,3874.47 372.56,3878.36 457.12,3877.63 2249,3878 118.03,3879.03 218.03,3879.03 318.03,3879.03 818.03,3879.03 918.03,3879.03 1718.03,3879.03 1818.03,3879.03 2318.03,3879.03 2418.03,3879.03 2518.03,3879.03 2918.03,3879.03 3518.03,3879.03 3618.03,3879.03 3718.03,3879.03 3818.03,3879.03 615,3889 3015,3890 4093,3892 2110.94,3895.91 959.7,3898.26 3359.7,3898.26 3468.64,3898.17 360.52,3898.61 468,3898.86 1068.43,3898.85 1560.2,3899.01 1668.18,3898.64 2759.99,3898.82 2868.83,3898.99 2145.13,3903.71 2269.66,3905.71 719,3913 3207,3913 -109.37,3914 1208,3921 3117,3922 3729,3929 2516,3930 1821,3935 2269.66,3946.22 360.52,3947.12 468,3947.37 959.7,3946.77 1068.43,3947.36 1560.2,3947.52 1668.18,3947.15 2160.13,3947.22 2759.99,3947.33 2868.83,3947.5 3359.7,3946.76 3468.64,3946.68 2608,3951 614,3972 2997,3977 168.03,3979.03 668.03,3979.03 768.03,3979.03 2468.03,3979.03 2568.03,3979.03 3068.03,3979.03 3168.03,3979.03 3668.03,3979.03 3768.03,3979.03 3620,3984 3830,3990 2011,3994 960.14,3995.28 3360.14,3995.27 3469.08,3995.19 360.95,3995.63 468.43,3995.87 1068.86,3995.87 1560.63,3996.03 1668.61,3995.66 2160.57,3995.73 2269.1,3995.73 2760.42,3995.84 2869.27,3996.01 2417,4012 731,4015 2512,4022 1430,4023 3018,4027 1216,4028 3115,4030 3613,4030 3744,4034 630,4037 1823,4041 2009,4042 361.15,4044.14 468.63,4044.38 960.33,4043.79 1069.06,4044.38 1668.8,4044.17 2160.76,4044.24 2269.29,4044.24 2760.62,4044.35 2869.46,4044.52 3360.33,4043.78 3469.27,4043.7 1560.83,4044.54 3209,4048 2612,4053 3833,4054 161,4090.44 207,4090 253,4090 715,4090.37 761,4090.37 807,4090 853,4090 1315,4090.37 1361,4090.37 1407,4090 1453,4090 3715,4090.37 3761,4090.37 3807,4090 3853,4090 3899,4090 69,4090.63 115,4090.63 577,4091 623,4091 669,4090.56 1177,4091 1223,4091 1269,4090.56 1915,4091.37 1961,4091.37 2007,4091 2053,4091 2515,4091.37 2561,4091.37 2607,4091 2653,4091 3577,4091 3623,4091 3669,4090.56 960.33,4092.3 1777,4092 1823,4092 1869,4091.56 2377,4092 2423,4092 2469,4091.56 3115,4092.37 3161,4092.37 3207,4092 3253,4092 3360.33,4092.29 3469.27,4092.21 361.15,4092.65 468.63,4092.89 1069.06,4092.88 1560.83,4093.05 1668.8,4092.68 2160.76,4092.74 2269.29,4092.74 2760.62,4092.86 2869.46,4093.03 2977,4093 3023,4093 3069,4092.56
  other v2: 840,340 640,2307 718.03,2325 912,2325 540,2340 898.81,2371.17 736.31,2464 915,2479.03 670,2486 754,2542 900,2542
GTR_REFCLK0_N: P1.34 TP9.1 U6.13 | length 699.9
  Top Layer w8.75: v1(2135.92,1666.99) 2137.69,1668.76 2137.69,1682.69 2158.13,1703.13 2158.13,1711.63 2157.63,1712.13 2157.63,1719.38 U6.13@2156,1721 ; P1.34@2170.75,1230.39 2171.37,1229.76 2171.37,1185.88 2173.22,1184.04 2173.22,1163.1
  Bottom Layer w8.75: 2141.04,1659.36 2141.04,1439.05 2112.22,1410.23 2112.22,1271.07 2173.18,1210.1 2173.18,1163.07 2168.06,1157.95 v1(2168.06,1155.44) TP9.1@2143.82,1155.44
GTR_REFCLK0_P: P1.32 TP5.1 U6.14 | length 699.9
  Top Layer w8.75: v1(2160.92,1666.99) 2160.92,1669.49 2155.73,1674.69 2155.73,1679.87 2172.88,1697.02 2172.88,1711.63 2173.38,1712.12 2173.38,1719.38 U6.14@2175,1721 ; 2187.97,1163.04 2187.97,1184.04 2189.81,1185.88 2189.81,1229.76 P1.32@2190.43,1230.39
  Bottom Layer w8.75: 2155.79,1659.36 2155.79,1432.94 2126.97,1404.12 2126.97,1277.18 2187.93,1216.21 2187.93,1163.07 2193.06,1157.95 v1(2193.06,1155.44) 2193.34,1155.72 2216.72,1155.72 TP5.1@2217,1156
GTR_REFCLK1_N: P1.31 TP10.1 U6.12 | length 488.6
  Top Layer w8.75: U6.12@2133,1744 2131.38,1745.62 2124.12,1745.62 2123.62,1746.12 2104.98,1746.12 2033.75,1674.89 2033.75,1631.29 2091.04,1574 2130,1574 2147,1557 2147,1518.04 2187.97,1477.07 2187.97,1449.96 2189.81,1448.12 2189.81,1404.24 P1.31@2190.43,1403.61
GTR_REFCLK1_P: P1.33 TP8.1 U6.11 | length 490.3
  Top Layer w8.75: U6.11@2133,1763 2131.38,1761.38 2124.12,1761.38 2123.62,1760.88 2098.88,1760.88 2019,1681 2019,1625.18 2173.22,1470.96 2173.22,1449.96 2171.37,1448.12 2171.37,1404.24 P1.33@2170.75,1403.61
GTR_REFCLK2_N: P1.28 TP6.1 U6.16 | length 528.3
  Top Layer w8.75: U6.16@2215,1721 2218.62,1717.38 2218.62,1695.52 2232.27,1681.87 2232.27,1672.48 v1(2227.17,1667.38) ; P1.28@2229.8,1230.39 2230.43,1231.01 2230.43,1274.89 2232.27,1276.73 2232.27,1297.73
  Bottom Layer w8.75: TP6.1@2214,1280 2214,1285.75 2225.41,1297.16 2225.41,1303.56 v1(2227.18,1305.33) 2227.18,1307.83 2232.3,1312.96 2232.3,1498.63 2232.3,1659.75 2227.17,1664.88 v1(2227.17,1667.38)
GTR_REFCLK2_P: P1.26 TP2.1 U6.17 | length 527.7
  Top Layer w8.75: U6.17@2235,1721 2233.38,1719.38 2233.38,1701.62 2247.02,1687.98 2247.02,1672.53 v1(2252.17,1667.38) ; 2247.02,1297.67 2247.02,1276.73 2248.86,1274.89 2248.86,1231.01 P1.26@2249.49,1230.39
  Bottom Layer w8.75: v1(2252.17,1667.38) 2252.17,1664.88 2247.05,1659.75 2247.05,1504.74 2247.05,1312.96 2252.18,1307.83 v1(2252.18,1305.33) 2253.95,1303.56 2253.95,1297.8 2266,1285.75 TP2.1@2266,1280
GTR_REFCLK3_N: P1.25 TP1.1 U6.20 | length 506.8
  Top Layer w8.75: P1.25@2249.49,1403.61 2248.86,1404.24 2248.86,1448.12 2247.02,1449.96 2247.02,1466.02 2402,1621 2402,1689.86 2330.98,1760.88 2286.37,1760.88 2285.87,1761.37 2278.62,1761.37 U6.20@2277,1763
GTR_REFCLK3_P: P1.27 TP3.1 U6.19 | length 506.4
  Top Layer w8.75: P1.27@2229.8,1403.61 2230.43,1404.24 2230.43,1448.12 2232.27,1449.96 2232.27,1472.13 2267.57,1507.43 2267.57,1548.57 2280,1561 2321.14,1561 2387.25,1627.11 2387.25,1683.75 2324.88,1746.12 2286.37,1746.12 2285.87,1745.63 2278.62,1745.63 U6.19@2277,1744
GTR_RX0_N: J18.10 P1.22 TVS1.1 TVS1.10 | length 2423.4
  Top Layer w8.75: v1(2286.17,1155.44) 2286.17,1157.95 2291.33,1163.1 2291.33,1184.04 2289.48,1185.88 2289.48,1229.76 P1.22@2288.86,1230.39 ; J18.10@3635.78,27 3629.56,33.22 3629.56,66 3621.9,73.66 3621.9,149 3658,185.1 v1@3658,243
  L6-SIG w5.5: v1(2286.17,1155.44) 2286.17,1158.17 2292.92,1164.92 2292.92,1183.93 2318.97,1209.98 2507.29,1209.98 2568.76,1148.5 2768.15,1148.5 2791.63,1125.03 2791.63,649.64 2818.48,622.79 3150.83,622.79 3410.12,363.5 3574.5,363.5 3656.35,281.65 3656.35,253.62 3662.6,247.37 v1(3662.6,244.14)
GTR_RX0_P: J18.9 P1.20 TVS1.2 TVS1.9 | length 2423.4
  Top Layer w8.75: P1.20@2308.54,1230.39 2307.92,1229.76 2307.92,1185.88 2306.08,1184.04 2306.08,1163.04 2311.17,1157.95 v1(2311.17,1155.44) ; TVS1.9@3604.69,82.5 3606.31,80.88 3606.31,68.39 3607.15,67.55 ; J18.9@3610.78,27 3614.56,30.78 3614.56,60.14 3607.15,67.55 ; v1@3643.25,243 3643.25,191.21 3607.15,155.11 3607.15,67.55
  L6-SIG w5.5: v1(2311.17,1155.44) 2311.17,1158.17 2304.42,1164.92 2304.42,1179.16 2323.73,1198.48 2502.52,1198.48 2564,1137 2763.39,1137 2780.13,1120.26 2780.13,644.87 2813.71,611.29 3146.07,611.29 3405.35,352 3459,352 3463.74,347.26 3463.74,341.26 3472,333 3485,333 3493.46,341.46 3493.46,348.65 3496.81,352 ; 3497,352 3569.74,352 3644.85,276.89 3644.85,253.62 3638.6,247.37 v1(3638.6,244.14)
GTR_RX1_N: C34.1 P1.16 | length 2816.1
  Top Layer w8.75: v1(446,482) 450.63,477.38 v1@452.5,477.38 ; v1@452.5,477.25 465.23,477.25 483.38,459.11 483.38,437.62 494,427 C34.1@494,426 ; v1(2345.22,1155.44) 2345.22,1157.95 2350.38,1163.1 2350.38,1184.04 2348.54,1185.88 2348.54,1229.76 P1.16@2347.91,1230.39
  L6-SIG w5.5: v1(446,482) 449.22,482 455.47,475.75 575,475.75 632.75,418 779.24,418 934.74,573.5 2302.5,573.5 2473.9,744.9 2473.9,887.87 2351.97,1009.8 2351.97,1145.97 2345.22,1152.72 v1(2345.22,1155.44)
GTR_RX1_P: C35.1 P1.14 | length 2816.3
  Top Layer w8.75: v1(446,458) 450.5,462.5 459.12,462.5 468.62,453 468.62,437.62 458,427 C35.1@458,426 ; P1.14@2367.6,1230.39 2366.97,1229.76 2366.97,1185.88 2365.13,1184.04 2365.13,1163.04 2370.22,1157.95 v1(2370.22,1155.44)
  L6-SIG w5.5: v1(446,458) 449.22,458 455.47,464.25 570.24,464.25 627.99,406.5 728.5,406.5 735.4,399.6 755.6,399.6 762.5,406.5 784,406.5 939.5,562 2307.26,562 2485.4,740.14 2485.4,892.63 2363.47,1014.56 2363.47,1145.97 2370.22,1152.72 v1(2370.22,1155.44)
GTR_RX2_N: P1.10
GTR_RX2_P: P1.08
GTR_RX3_N: P1.04
GTR_RX3_P: P1.02
GTR_TX0_N: C42.1 P1.21 | length 2448.8
  Top Layer w8.75: v1(2286.17,1328.67) 2286.17,1331.18 2291.33,1336.33 2291.33,1357.27 2289.48,1359.11 2289.48,1402.99 P1.21@2288.86,1403.61 ; v1@3562.88,245 3562.88,212.89 3562.88,204.75 3568,199.62 3568.38,199.62 3574,194 C42.1@3574,193
  L3-SIG w5.5: v1(2286.17,1328.67) 2286.17,1325.95 2292.92,1319.2 2292.92,1297.95 2469.98,1120.9 2469.98,879.72 2565,784.7 2565,289.74 2717.74,137 3543,137 3561.25,155.25 3561.25,235.53 3567.5,241.78 v1(3567.5,245)
GTR_TX0_P: C41.1 P1.19 | length 2449.6
  Top Layer w8.75: P1.19@2308.54,1403.61 2307.92,1402.99 2307.92,1359.11 2306.08,1357.27 2306.08,1336.27 2311.17,1331.18 v1(2311.17,1328.67) ; C41.1@3537,193 3537,194 3542.62,199.62 3543,199.62 3548.12,204.75 3548.12,219 v1@3548.13,245
  L3-SIG w5.5: v1(2311.17,1328.67) 2311.17,1325.95 2304.42,1319.2 2304.42,1302.72 2481.48,1125.66 2481.48,884.48 2576.5,789.46 2576.5,294.5 2722.5,148.5 3433.5,148.5 3438,153 3438,166 3447,175 3469,175 3476,168 3476,152 3479.5,148.5 3538.24,148.5 3549.75,160.01 3549.75,235.53 3543.5,241.78 v1(3543.5,245)
GTR_TX1_N: C32.1 P1.15 | length 2731.2
  Top Layer w8.75: C32.1@608,426 608,427 618.62,437.62 618.62,471.11 635.27,487.75 v1@687,487.75 ; v1(2345.22,1328.67) 2345.22,1331.18 2350.38,1336.33 2350.38,1357.27 2348.54,1359.11 2348.54,1402.99 P1.15@2347.91,1403.61
  L6-SIG w5.5: v1(689.09,492.39) 692.32,492.39 698.57,486.14 779,486.14 931.86,639 2282.5,639 2411.5,768 2411.5,896.26 2233.14,1074.63 2233.14,1183.56 2351.97,1302.4 2351.97,1319.2 2345.22,1325.95 v1(2345.22,1328.67)
GTR_TX1_P: C31.1 P1.13 | length 2731.4
  Top Layer w8.75: C31.1@644,426 644,427 633.38,437.62 633.38,465 641.38,473 v1@687,473 ; P1.13@2367.6,1403.61 2366.97,1402.99 2366.97,1359.11 2365.13,1357.27 2365.13,1336.27 2370.22,1331.18 v1(2370.22,1328.67)
  L6-SIG w5.5: v1(689.09,468.39) 692.32,468.39 698.57,474.64 723,474.64 ; 723.5,474.5 730.8,467.2 750.2,467.2 757.64,474.64 783.76,474.64 936.62,627.5 2287.26,627.5 2423,763.24 2423,901.02 2244.64,1079.39 2244.64,1178.8 2363.47,1297.64 2363.47,1319.2 2370.22,1325.95 v1(2370.22,1328.67)
GTR_TX2_N: C55.1 P1.09 | length 1339
  Top Layer w8.75: v1(2404.9,1328.05) 2404.9,1330.55 2410.06,1335.71 2410.06,1356.65 2408.22,1358.49 P1.09@2408.22,1402.36 ; P1.09@2406.97,1403.61 P1.09@2407.59,1402.99 ; v1(3372.15,1782.84) 3373.92,1781.07 3381.21,1781.07 3384.07,1778.21 3412.87,1778.21 3427.21,1778.21 3436,1787 C55.1@3437,1787
  L3-SIG w5.5: v1(2404.9,1328.05) 2404.9,1330.77 2411.65,1337.52 2411.65,1368.56 2479.03,1435.94 2504.07,1435.94 2586.24,1518.11 2586.24,1543.91 2724.78,1682.45 3247.94,1682.45 3342.08,1776.59 3362.68,1776.59 3368.93,1782.84 v1(3372.15,1782.84)
GTR_TX2_P: C54.1 P1.07 | length 1330.3
  Top Layer w8.75: P1.07@2426.03,1402.99 P1.07@2426.65,1403.61 ; P1.07@2426.65,1402.36 2426.65,1358.49 2424.81,1356.65 2424.81,1335.64 2429.9,1330.55 v1(2429.9,1328.05) ; v1(3372.15,1758.84) 3373.92,1760.61 3381.21,1760.61 3384.07,1763.46 3406.76,1763.46 3427.21,1763.46 3436,1754.67 C54.1@3437,1754.67
  L3-SIG w5.5: v1(2429.9,1328.05) 2429.9,1330.77 2423.15,1337.52 2423.15,1363.8 2483.79,1424.44 2508.83,1424.44 2597.74,1513.34 2597.74,1539.15 2634.24,1575.65 2651.93,1575.65 2663.64,1587.35 2663.64,1605.05 2729.54,1670.95 3252.7,1670.95 3346.84,1765.09 3362.68,1765.09 3368.93,1758.84 v1(3372.15,1758.84)
GTR_TX3_N: C53.1 P1.03 | length 1319.1
  Top Layer w8.75: v1(2463.96,1328.05) 2463.96,1330.55 2469.12,1335.71 2469.12,1356.65 2467.27,1358.49 P1.03@2467.27,1402.36 ; P1.03@2466.02,1403.61 P1.03@2466.65,1402.99 ; v1(3405,1720) 3407.5,1720 3412.63,1714.88 3427.54,1714.88 3436,1723.33 C53.1@3437,1723.33
  L3-SIG w5.5: v1(2463.96,1328.05) 2463.96,1330.77 2470.71,1337.52 2470.71,1370.95 2498.7,1398.94 2626.84,1398.94 2644.28,1416.38 2644.28,1507.73 2775.05,1638.5 3223.09,1638.5 3253.59,1608 3268.74,1608 3373.99,1713.25 3395.53,1713.25 3402.28,1720 v1(3405,1720)
GTR_TX3_P: C52.1 P1.01 | length 1316.2
  Top Layer w8.75: P1.01@2485.08,1402.99 P1.01@2485.71,1403.61 ; P1.01@2485.71,1402.36 2485.71,1358.49 2483.87,1356.65 2483.87,1335.64 2488.96,1330.55 v1(2488.96,1328.05) ; v1(3405,1695) 3407.5,1695 3412.63,1700.12 3426.88,1700.12 3436,1691 C52.1@3437,1691
  L3-SIG w5.5: v1(2488.96,1328.05) 2488.96,1330.77 2482.21,1337.52 2482.21,1366.19 2503.46,1387.44 2631.6,1387.44 2655.78,1411.62 2655.78,1502.96 2691.82,1539 2719,1539 2728.57,1548.57 2728.57,1575.76 2779.82,1627 3218.32,1627 3248.82,1596.5 3273.5,1596.5 3378.75,1701.75 3395.53,1701.75 3402.28,1695 v1(3405,1695)
I2C1_SCL: J23.19 R33.2 R100.1 R102.1 TP7.1 U6.9 | length 2085.9
  Top Layer w8: R102.1@1651,1643 1651,1713 1674,1736 v1(1725,1736) R100.1@1725,1683 ; R33.2@2071,1819 2096,1819 2112,1803 U6.9@2133,1803
  L6-SIG w8: v1(1725,1736) 1763,1774 1916,1774 1961,1819 v1(2095,1819)
  Bottom Layer w8: v1(1725,1736) 1674,1736 1659,1721 1659,1054 1738,975 1967,975 2043,899 2043,817 J23.19@1993,767 TP7.1@1992.98,700.8
I2C1_SDA: J23.21 R34.2 R101.1 R103.2 TP4.1 U6.8 | length 2087.8
  Top Layer w8: R101.1@1691,1683 v1@1690.99,1712.01 ; R103.2@1765,1643 v1(1765,1677) 1765,1720 1950,1905 2048,1905 2071,1882 R34.2@2071,1855 2087,1855 2119,1823 U6.8@2133,1823
  L6-SIG w8: v1(1690.98,1712.02) v1@1692.02,1713.07
  Bottom Layer w8: v1(1765,1677) 1729.98,1712.02 v1(1690.98,1712.02) 1690.98,1642.98 1679,1631 1679,1069 1753,995 2041,995 2142,894 2142,816 J23.21@2093,767 2092.66,766.66 2092.66,701.09 TP4.1@2092.32,700.75
I2C1_SELECT_CL: P1.83 R100.2 R103.1 | length 258.6
  Top Layer w8: P1.83@1678.62,1403.61 1678.62,1545.62 1725,1592 R103.1@1725,1643
I2C1_SELECT_DA: P1.85 R101.2 R102.2 | length 253.5
  Top Layer w8: P1.85@1658.94,1403.61 1658.94,1559.94 1692,1593 1692,1642 R101.2@1691,1643
IO_L1_N: P1.61 U10.3 | length 1278.8
  Top Layer w8.75: U10.3@807,1257 834.49,1257 852.61,1238.88 866.69,1238.88 869.61,1241.79 876.9,1241.79 v1(878.67,1243.56) ; 1859.63,1318.72 1859.63,1318.14 ; v1(1864.74,1298.85) 1864.74,1301.36 1859.63,1306.47 1859.63,1318.14 ; P1.61@1895.51,1403.26 P1.61@1895.16,1403.61 1894.51,1402.97 1894.51,1366.72 1892.63,1364.83 1892.63,1351.13 1859.63,1318.14
  L3-SIG w5.5: v1(878.67,1243.56) 881.89,1243.56 888.14,1237.31 912.58,1237.31 986.07,1237.31 1103.76,1355 1833.1,1355 1857.99,1330.11 1857.99,1308.33 1864.74,1301.58 v1(1864.74,1298.85)
IO_L1_P: P1.63 U10.1 | length 1258.9
  Top Layer w8.75: U10.1@807,1206 834.49,1206 852.61,1224.12 866.81,1224.12 869.61,1221.33 876.9,1221.33 v1(878.67,1219.56) ; v1(1839.74,1298.85) 1839.74,1301.36 1844.88,1306.5 1844.88,1324.83 1853.52,1333.47 1854.1,1333.47 1877.88,1357.24 1877.88,1364.82 1875.47,1367.22 P1.63@1875.47,1403.61
  L3-SIG w5.5: v1(878.67,1219.56) 881.89,1219.56 888.14,1225.81 917.35,1225.81 990.84,1225.81 1108.52,1343.5 1828.34,1343.5 1846.49,1325.35 1846.49,1308.33 1839.74,1301.58 v1(1839.74,1298.85)
IO_L2_N: P1.57 U10.5 | length 1305.7
  Top Layer w8.75: U10.5@807,1308 835.96,1308 841.59,1302.37 916.97,1302.37 982.88,1368.28 982.88,1372.31 988.03,1377.47 v1(988.03,1379.97) ; P1.57@1934.53,1403.61 1935.15,1404.24 1935.15,1448.12 1936.99,1449.96 1937,1470.96
  L3-SIG w5.5: v1(988.03,1379.97) 990.31,1382.25 999.15,1382.25 1048.06,1431.16 1931.76,1431.16 1938.65,1438.06 1938.65,1469.08 1931.9,1475.83 v1(1931.9,1478.56)
IO_L2_P: P1.55 U10.4 | length 1327.2
  Top Layer w8.75: U10.4@807,1282.5 835.96,1282.5 841.09,1287.62 923.08,1287.62 993.3,1357.85 997.34,1357.85 1002.5,1363 v1(1005,1363) ; 1951.75,1470.9 1951.75,1449.96 1953.59,1448.12 1953.59,1404.24 P1.55@1954.21,1403.61
  L3-SIG w5.5: v1(1005,1363) 1007.28,1365.28 1007.28,1374.12 1052.82,1419.66 1936.52,1419.66 1950.15,1433.29 1950.15,1469.08 1956.9,1475.83 v1(1956.9,1478.56)
IO_L3_N: P1.51 U10.7 | length 1345.4
  Top Layer w8.75: U10.7@807,1359 835.96,1359 841.34,1353.62 857.84,1353.62 860.94,1356.73 868.23,1356.73 v1(870,1358.5) ; v1(1946.08,1331.96) 1948.59,1331.96 1953.71,1326.84 1979.98,1326.84 1996.05,1342.91 1996.05,1357.27 1994.21,1359.11 1994.21,1402.99 P1.51@1993.58,1403.61
  L3-SIG w5.5: v1(870,1358.5) 873.22,1358.5 879.47,1352.25 898.21,1352.25 934.96,1315.5 1006.2,1315.5 1084.7,1394 1854.26,1394 1923.05,1325.21 1936.61,1325.21 1943.36,1331.96 v1(1946.08,1331.96)
IO_L3_P: P1.49 U10.6 | length 1369.7
  Top Layer w8.75: U10.6@807,1333.5 835.96,1333.5 841.34,1338.88 858.34,1338.88 860.94,1336.27 868.23,1336.27 v1(870,1334.5) ; v1(1946.08,1306.96) 1948.59,1306.96 1953.71,1312.09 1986.09,1312.09 2010.8,1336.8 2010.8,1357.27 2012.64,1359.11 2012.64,1402.99 P1.49@2013.27,1403.61
  L3-SIG w5.5: v1(870,1334.5) 873.22,1334.5 879.47,1340.75 893.45,1340.75 930.2,1304 1010.96,1304 1089.46,1382.5 1849.5,1382.5 1918.29,1313.71 1936.61,1313.71 1943.36,1306.96 v1(1946.08,1306.96)
IO_L4_N: P1.69 U10.9 | length 1295.8
  Top Layer w8.75: U10.9@807,1410 835.96,1410 841.59,1404.38 901.68,1404.45 904.53,1407.3 911.82,1407.3 v1(913.59,1409.07) ; v1(1814.42,1512.81) 1814.42,1510.31 1819.54,1505.18 1819.54,1472.97 ; 1819.51,1472.94 1819.51,1449.33 1817.67,1447.49 P1.69@1817.67,1403.61 ; P1.69@1817.67,1403.61 1817.04,1402.99 P1.69@1817.67,1403.61
  L3-SIG w5.5: v1(913.59,1409.07) 916.81,1409.07 923.06,1402.82 939.64,1402.82 1116.81,1580 1728.88,1580 1767.12,1541.76 1767.12,1499.88 1780.5,1486.5 1813,1486.5 1821.17,1494.67 1821.17,1503.34 1814.42,1510.09 v1(1814.42,1512.81)
IO_L4_P: P1.67 U10.8 | length 1316.3
  Top Layer w8.75: U10.8@807,1384.5 835.96,1384.5 841.09,1389.62 901.68,1389.7 904.53,1386.84 911.82,1386.84 v1(913.59,1385.07) ; 1834.26,1466.83 1834.26,1449.33 1836.1,1447.49 P1.67@1836.1,1403.61 P1.67@1836.73,1402.99 ; 1834.29,1466.86 1834.29,1505.18 1839.42,1510.31 v1(1839.42,1512.81)
  L3-SIG w5.5: v1(913.59,1385.07) 916.81,1385.07 923.06,1391.32 944.4,1391.32 1121.58,1568.5 1724.12,1568.5 1755.62,1537 1755.62,1495.12 1775.74,1475 1822,1475 1832.67,1485.67 1832.67,1493.33 1832.67,1503.34 1839.42,1510.09 v1(1839.42,1512.81)
IO_L5_N: P1.75 U11.3 | length 1448.8
  Top Layer w8.75: U11.3@807,887 834.49,887 852.61,868.88 866.69,868.88 869.61,871.79 876.9,871.79 v1(878.67,873.56) ; v1(1755,1315) 1756.77,1316.77 1756.77,1324.06 1759.83,1327.12 1759.83,1357.27 1757.99,1359.11 1757.99,1402.99 P1.75@1757.36,1403.61
  L3-SIG w5.5: v1(878.67,873.56) 882.05,873.56 888.3,867.31 894.46,867.31 900.03,872.88 900.03,920.58 855,965.62 855,1056.26 945.17,1146.43 1443.52,1146.43 1554.72,1257.63 1589.63,1257.63 1612,1280 1634,1280 1656.37,1257.63 1726.46,1257.63 1761.25,1292.42 1761.25,1305.53 1755,1311.78 v1(1755,1315)
IO_L5_P: P1.73 U11.1 | length 1452.7
  Top Layer w8.75: U11.1@807,836 834.49,836 852.61,854.12 866.81,854.12 869.61,851.33 876.9,851.33 v1(878.67,849.56) ; P1.73@1777.05,1403.61 1776.42,1402.99 1776.42,1359.11 1774.58,1357.27 1774.58,1326.71 1777.23,1324.06 1777.23,1316.77 v1(1779,1315) v1@1781.55,1312.45
  L3-SIG w5.5: v1(878.67,849.56) 881.89,849.56 888.14,855.81 899.23,855.81 911.53,868.12 911.53,925.35 866.5,970.38 866.5,1051.5 949.93,1134.93 1448.29,1134.93 1559.48,1246.13 1731.22,1246.13 1772.75,1287.66 1772.75,1305.53 1779,1311.78 v1(1779,1315)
